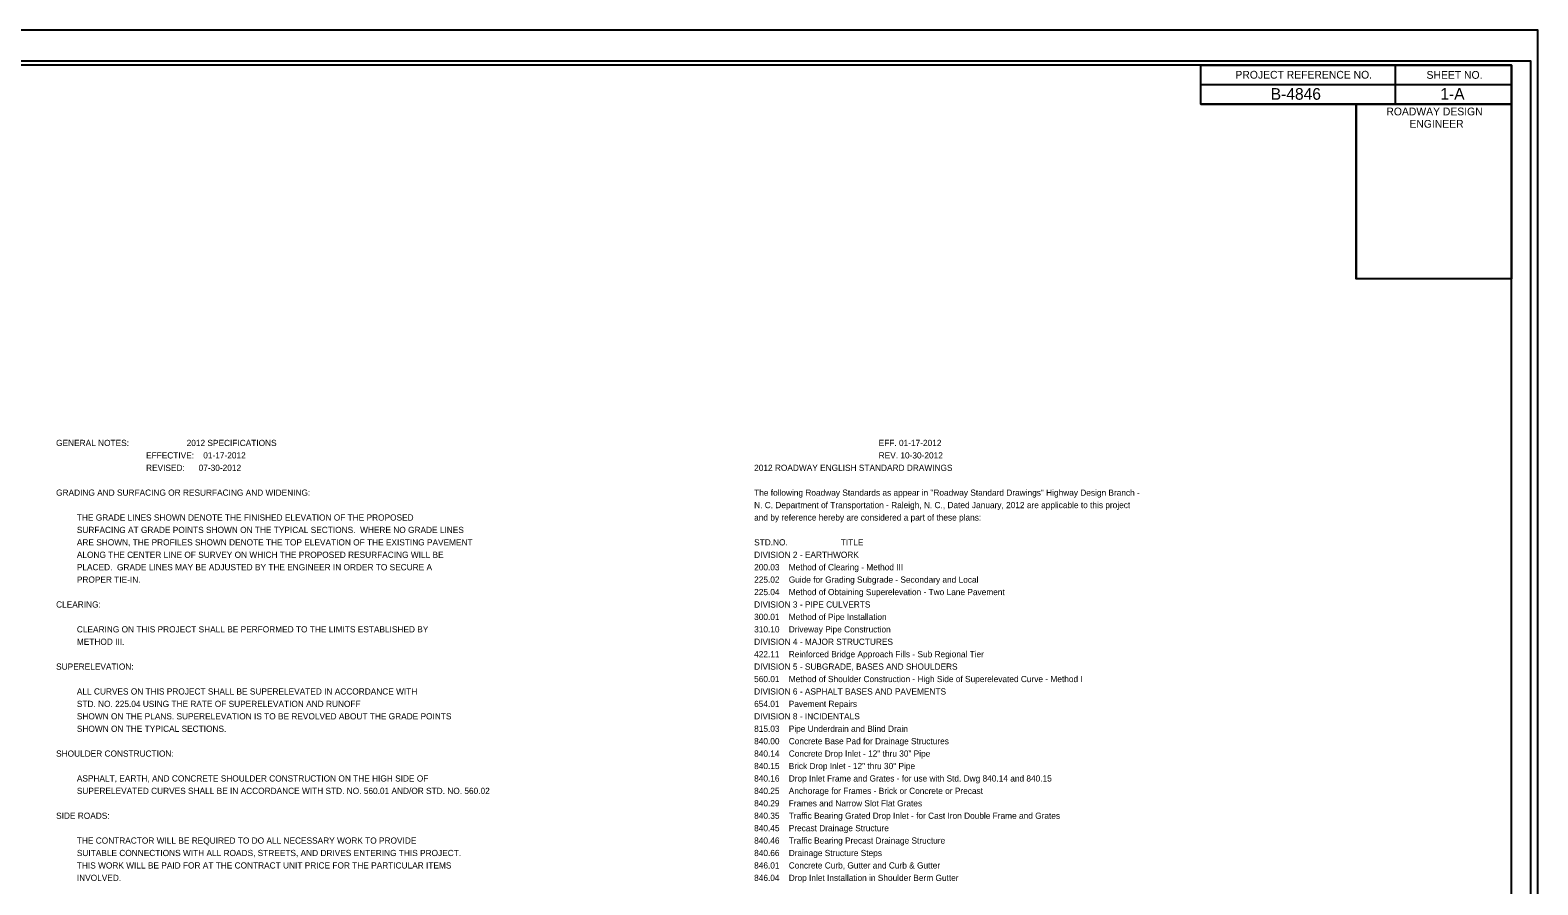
# Model space of a CAD drawing. Extents: x 573606 to 575290, y -53273 to -52178.
# Drawn here: x 574319 to 575290, y -52728 to -52178 of the extents above; entities that cross this region are included whole.
import ezdxf

# ---------------------------------------------------------------- set-up
doc = ezdxf.new("R2010")
doc.units = 0
for name, color, linetype in [('Default', 7, 'Continuous'), ('Sheet Cutting Line CELL', 7, 'Continuous'), ('Sheet Data Field CELL', 7, 'Continuous'), ('Sheet Plan CELL', 7, 'Continuous'), ('Sheet Plot Border Inside CELL', 7, 'Continuous'), ('Sheet Plot Border Outside CELL', 7, 'Continuous')]:
    doc.layers.add(name, color=color, linetype=linetype)

msp = doc.modelspace()

# ---------------------------------------------------------------- linework, layer by layer
at = {"layer": 'Sheet Cutting Line CELL'}
msp.add_line((575289.96, -52177.62), (573606.46, -52177.62), dxfattribs=at)
at = {"layer": 'Sheet Plan CELL'}
for p, q in [((575197.96, -52200.17), (575197.96, -52225.17)), ((575072.91, -52212.67), (575272.96, -52212.67)), ((575072.91, -52225.17), (575272.96, -52225.17)), ((575072.91, -52225.17), (575272.96, -52225.17)), ((575172.96, -52225.17), (575172.96, -52337.62))]:
    msp.add_line(p, q, dxfattribs=at)
for points in [[(575272.96, -52200.12), (573772.96, -52200.12), (573772.96, -53250.12), (575272.96, -53250.12)], [(575072.91, -52200.12), (575272.96, -52200.12), (575272.96, -52225.17), (575072.91, -52225.17)], [(575172.96, -52225.17), (575272.96, -52225.17), (575272.96, -52337.67), (575172.96, -52337.67)]]:
    msp.add_lwpolyline(points, close=True, dxfattribs=at)
at = {"layer": 'Sheet Plot Border Inside CELL'}
msp.add_lwpolyline([(573619.46, -53252.62), (575285.46, -53252.62), (575285.46, -52197.62), (573619.46, -52197.62)], close=True, dxfattribs=at)
at = {"layer": 'Sheet Plot Border Outside CELL'}
msp.add_lwpolyline([(573606.46, -53272.62), (575289.96, -53272.62), (575289.96, -52177.62), (573606.46, -52177.62)], close=True, dxfattribs=at)

# ---------------------------------------------------------------- texts
at = {"layer": 'Default'}
for s, p in [('GENERAL NOTES:                         2012 SPECIFICATIONS', (574335.28, -52445.36)), ('                                                      EFF. 01-17-2012', (574785.02, -52445.36)), ('                                       EFFECTIVE:    01-17-2012', (574335.28, -52453.36)), ('                                                      REV. 10-30-2012', (574785.02, -52453.36)), ('                                       REVISED:      07-30-2012', (574335.28, -52461.36)), ('2012 ROADWAY ENGLISH STANDARD DRAWINGS', (574785.02, -52461.36)), ('GRADING AND SURFACING OR RESURFACING AND WIDENING:  ', (574335.28, -52477.36)), ('The following Roadway Standards as appear in "Roadway Standard Drawings" Highway Design Branch -', (574785.02, -52477.36)), ('N. C. Department of Transportation - Raleigh, N. C., Dated January, 2012 are applicable to this project', (574785.02, -52485.36)), ('         THE GRADE LINES SHOWN DENOTE THE FINISHED ELEVATION OF THE PROPOSED ', (574335.28, -52493.36)), ('and by reference hereby are considered a part of these plans:', (574785.02, -52493.36)), ('         SURFACING AT GRADE POINTS SHOWN ON THE TYPICAL SECTIONS.  WHERE NO GRADE LINES ', (574335.28, -52501.36)), ('         ARE SHOWN, THE PROFILES SHOWN DENOTE THE TOP ELEVATION OF THE EXISTING PAVEMENT ', (574335.28, -52509.36)), ('         ALONG THE CENTER LINE OF SURVEY ON WHICH THE PROPOSED RESURFACING WILL BE ', (574335.28, -52517.36)), ('STD.NO.                       TITLE', (574785.02, -52509.36)), ('DIVISION 2 - EARTHWORK', (574785.02, -52517.36)), ('         PLACED.  GRADE LINES MAY BE ADJUSTED BY THE ENGINEER IN ORDER TO SECURE A ', (574335.28, -52525.36)), ('200.03    Method of Clearing - Method III', (574785.02, -52525.36)), ('         PROPER TIE-IN.  ', (574335.28, -52533.36)), ('225.02    Guide for Grading Subgrade - Secondary and Local', (574785.02, -52533.36)), ('225.04    Method of Obtaining Superelevation - Two Lane Pavement', (574785.02, -52541.36)), ('CLEARING:  ', (574335.28, -52549.36)), ('DIVISION 3 - PIPE CULVERTS', (574785.02, -52549.36)), ('         CLEARING ON THIS PROJECT SHALL BE PERFORMED TO THE LIMITS ESTABLISHED BY ', (574335.28, -52565.36)), ('300.01    Method of Pipe Installation ', (574785.02, -52557.36)), ('310.10    Driveway Pipe Construction', (574785.02, -52565.36)), ('         METHOD III.', (574335.28, -52573.36)), ('DIVISION 4 - MAJOR STRUCTURES', (574785.02, -52573.36)), ('422.11    Reinforced Bridge Approach Fills - Sub Regional Tier', (574785.02, -52581.36)), ('SUPERELEVATION:  ', (574335.28, -52589.36)), ('DIVISION 5 - SUBGRADE, BASES AND SHOULDERS', (574785.02, -52589.36)), ('560.01    Method of Shoulder Construction - High Side of Superelevated Curve - Method I', (574785.02, -52597.36)), ('         ALL CURVES ON THIS PROJECT SHALL BE SUPERELEVATED IN ACCORDANCE WITH', (574335.28, -52605.36)), ('         STD. NO. 225.04 USING THE RATE OF SUPERELEVATION AND RUNOFF ', (574335.28, -52613.36)), ('654.01    Pavement Repairs', (574785.02, -52613.36)), ('DIVISION 6 - ASPHALT BASES AND PAVEMENTS', (574785.02, -52605.36)), ('         SHOWN ON THE PLANS. SUPERELEVATION IS TO BE REVOLVED ABOUT THE GRADE POINTS ', (574335.28, -52621.36)), ('DIVISION 8 - INCIDENTALS', (574785.02, -52621.36)), ('         SHOWN ON THE TYPICAL SECTIONS.  ', (574335.28, -52629.36)), ('815.03    Pipe Underdrain and Blind Drain', (574785.02, -52629.36)), ('840.00    Concrete Base Pad for Drainage Structures', (574785.02, -52637.36)), ('SHOULDER CONSTRUCTION:  ', (574335.28, -52645.36)), ('840.14    Concrete Drop Inlet - 12" thru 30" Pipe', (574785.02, -52645.36)), ('840.15    Brick Drop Inlet - 12" thru 30" Pipe', (574785.02, -52653.36)), ('         ASPHALT, EARTH, AND CONCRETE SHOULDER CONSTRUCTION ON THE HIGH SIDE OF', (574335.28, -52661.36)), ('840.16    Drop Inlet Frame and Grates - for use with Std. Dwg 840.14 and 840.15', (574785.02, -52661.36)), ('         SUPERELEVATED CURVES SHALL BE IN ACCORDANCE WITH STD. NO. 560.01 AND/OR STD. NO. 560.02', (574335.28, -52669.36)), ('840.25    Anchorage for Frames - Brick or Concrete or Precast', (574785.02, -52669.36)), ('840.29    Frames and Narrow Slot Flat Grates', (574785.02, -52677.36)), ('SIDE ROADS:  ', (574335.28, -52685.36)), ('840.35    Traffic Bearing Grated Drop Inlet - for Cast Iron Double Frame and Grates', (574785.02, -52685.36)), ('         THE CONTRACTOR WILL BE REQUIRED TO DO ALL NECESSARY WORK TO PROVIDE ', (574335.28, -52701.36)), ('840.45    Precast Drainage Structure', (574785.02, -52693.36)), ('840.46    Traffic Bearing Precast Drainage Structure', (574785.02, -52701.36)), ('         SUITABLE CONNECTIONS WITH ALL ROADS, STREETS, AND DRIVES ENTERING THIS PROJECT.  ', (574335.28, -52709.36)), ('840.66    Drainage Structure Steps', (574785.02, -52709.36)), ('         THIS WORK WILL BE PAID FOR AT THE CONTRACT UNIT PRICE FOR THE PARTICULAR ITEMS ', (574335.28, -52717.36)), ('846.01    Concrete Curb, Gutter and Curb & Gutter', (574785.02, -52717.36)), ('         INVOLVED.  ', (574335.28, -52725.36)), ('846.04    Drop Inlet Installation in Shoulder Berm Gutter', (574785.02, -52725.36))]:
    msp.add_text(s, height=4, dxfattribs=at).set_placement(p)
at = {"layer": 'Sheet Data Field CELL'}
for s, p in [('B-4846', (575117.87, -52222.42)), ('1-A', (575227.13, -52222.37))]:
    msp.add_text(s, height=7.5, dxfattribs=at).set_placement(p)
at = {"layer": 'Sheet Plan CELL'}
for s, height, p in [('PROJECT REFERENCE NO.', 5.0001, (575095.11, -52208.82)), ('SHEET NO.', 5, (575218.26, -52208.92)), ('ROADWAY DESIGN', 5.0001, (575192.36, -52232.47)), ('ENGINEER', 5, (575207.21, -52240.42))]:
    msp.add_text(s, height=height, dxfattribs=at).set_placement(p)

doc.saveas('drawing.dxf')
